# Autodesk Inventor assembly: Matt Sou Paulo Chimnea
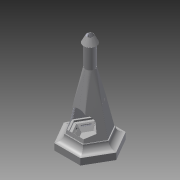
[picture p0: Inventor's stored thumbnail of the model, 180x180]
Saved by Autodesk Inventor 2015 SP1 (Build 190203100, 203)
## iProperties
Created: 2014-12
Part Number: Matt Sou Paulo Chimnea
Document SubType Name: Assembly
Designer: rsheridan
Author: rsheridan
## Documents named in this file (6)
- \\psf\Home\Desktop\Matt Sou Paulo Chimnea.iam
- \\psf\Home\Documents\Inventor\Sau Paulo Chimnea\Base Assembly.iam
- \\psf\Home\Documents\Inventor\Sau Paulo Chimnea\Upper_Assy.iam
- \\psf\Home\Documents\Inventor\Sau Paulo Chimnea\RivNut.ipt
- \\psf\Home\Documents\Inventor\Sau Paulo Chimnea\ANSI B18.6.7M - M5x0.8 x 6(4).ipt
- \\psf\Home\Documents\Inventor\Sau Paulo Chimnea\Body Assembly New.iam
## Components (11 placed, 5 different names)
1. Base Assembly:1 [sub-assembly] — Mate:1, Mate:2, Mate:3, Mate:6
2. Body Assembly New:1 [sub-assembly] — Mate:1, Mate:2, Mate:3, Mate:4, Mate:5, Insert:1
3. Upper_Assy:1 [sub-assembly] — Mate:4, Mate:5, Mate:6, Insert:2
4. RivNut:1 — Insert:1
5. ANSI B18.6.7M - M5x0.8 x 6(4):1 — Insert:2
6. RivNut:2
7. ANSI B18.6.7M - M5x0.8 x 6(4):2
8. RivNut:4
9. ANSI B18.6.7M - M5x0.8 x 6(4):4
10. RivNut:5
11. ANSI B18.6.7M - M5x0.8 x 6(4):5
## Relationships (8: Mate 6, Insert 2)
- Mate:1: Base Assembly:1 ↔ Body Assembly New:1
- Mate:2: Base Assembly:1 ↔ Body Assembly New:1
- Mate:3: Base Assembly:1 ↔ Body Assembly New:1
- Mate:4: Body Assembly New:1 ↔ Upper_Assy:1
- Mate:5: Body Assembly New:1 ↔ Upper_Assy:1
- Mate:6: Base Assembly:1 ↔ Upper_Assy:1
- Insert:1: Body Assembly New:1 ↔ RivNut:1
- Insert:2: Upper_Assy:1 ↔ ANSI B18.6.7M - M5x0.8 x 6(4):1
